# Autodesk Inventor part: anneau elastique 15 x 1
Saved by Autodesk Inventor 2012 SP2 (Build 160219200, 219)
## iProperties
Created: 2013-04
Part Number: anneau elastique 15 x 1
Material: Default
Document SubType Name: Modeling
Designer: papa
Density: 1 g/cm^3
Mass: 0.0927161 g
Surface Area: 3.0673 cm^2
Volume: 0.0927161 cm^3
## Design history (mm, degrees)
node "anneau elastique 15 x 11"
node "anneau elastique 15 x 1"
node "Base1"
